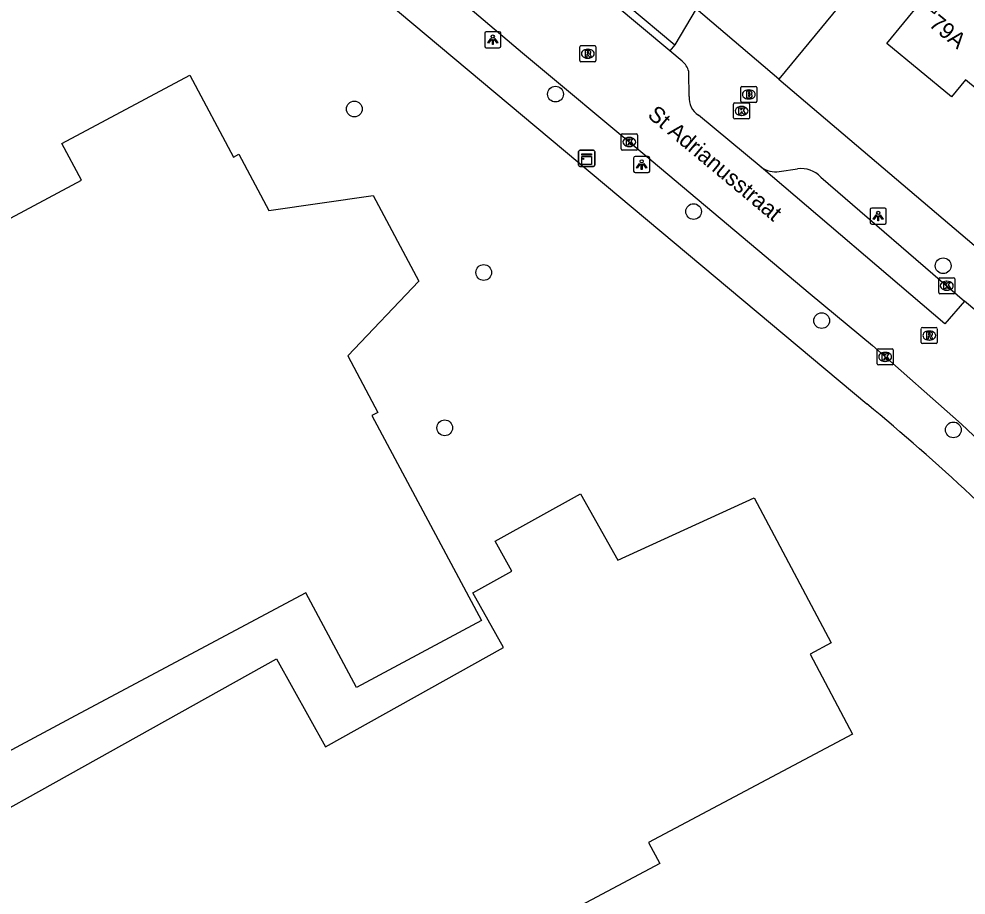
# Model space of a CAD drawing. Extents: x 162074 to 163034, y 381824 to 382557.
# Drawn here: x 162521.9 to 162580.8, y 382015.9 to 382070.3 of the extents above; entities that cross this region are included whole.
import ezdxf

# ---------------------------------------------------------------- set-up
doc = ezdxf.new("R2010")
doc.units = 0
for name, color, linetype in [('IMGEO_Boom', 7, 'Continuous'), ('IMGEO_Brandkraan', 7, 'Continuous'), ('IMGEO_Kast', 7, 'Continuous'), ('IMGEO_Kolk', 7, 'Continuous'), ('IMGEO_Lichtpunt', 7, 'Continuous'), ('IMGEO_Openbare_ruimte_label', 7, 'Continuous'), ('IMGEO_Pand', 7, 'Continuous'), ('IMGEO_Pand_nummerreeks', 7, 'Continuous'), ('IMGEO_Pand_vergunning_verleend', 7, 'Continuous'), ('IMGEO_Rijbaan_lokaal_open', 7, 'Continuous'), ('IMGEO_Rioolput', 7, 'Continuous'), ('IMGEO_Voetpad_open', 7, 'Continuous')]:
    doc.layers.add(name, color=color, linetype=linetype)

msp = doc.modelspace()

# ---------------------------------------------------------------- linework, layer by layer
at = {"layer": 'IMGEO_Boom'}
for centre in [(162555.268, 382065.67), (162542.77, 382064.746), (162563.851, 382058.369), (162579.361, 382055), (162550.809, 382054.581), (162571.812, 382051.59), (162548.386, 382044.926), (162579.99, 382044.797)]:
    msp.add_circle(centre, 0.489, dxfattribs=at)
at = {"layer": 'IMGEO_Brandkraan'}
for p, q in [((162566.781, 382065.222), (162566.781, 382066.074)), ((162566.856, 382066.148), (162567.708, 382066.148)), ((162567.782, 382066.074), (162567.782, 382065.222)), ((162567.292, 382065.368), (162567.267, 382065.368)), ((162567.269, 382065.928), (162567.294, 382065.928)), ((162567.708, 382065.148), (162566.856, 382065.148))]:
    msp.add_line(p, q, dxfattribs=at)
for points in [[(162566.781, 382065.222), (162566.781, 382066.074)], [(162566.856, 382066.148), (162567.708, 382066.148)], [(162567.782, 382066.074), (162567.782, 382065.222)], [(162567.129, 382065.848), (162567.129, 382065.448), (162567.342, 382065.448)], [(162567.36, 382065.848), (162567.129, 382065.848)], [(162567.308, 382065.767), (162567.254, 382065.767), (162567.254, 382065.691)], [(162567.254, 382065.691), (162567.307, 382065.691)], [(162567.316, 382065.615), (162567.254, 382065.615), (162567.254, 382065.534)], [(162567.254, 382065.534), (162567.316, 382065.534)], [(162567.708, 382065.148), (162566.856, 382065.148)]]:
    msp.add_lwpolyline(points, dxfattribs=at)
for centre, radius, start, end in [((162566.858, 382066.072), 0.0765, 91.55205, 178.44795), ((162566.858, 382066.072), 0.0765, 91.55205, 178.44795), ((162567.706, 382066.072), 0.0765, 1.55205, 88.44795), ((162567.706, 382066.072), 0.0765, 1.55205, 88.44795), ((162567.309, 382065.729), 0.0379, 267.82845, 90.93552), ((162567.317, 382065.574), 0.0404, 269.87594, 90.50774), ((162567.348, 382065.699), 0.251, 268.66757, 293.53466), ((162567.364, 382065.703), 0.145, 59.4692, 91.53667), ((162567.389, 382065.75), 0.0922, 285.51372, 58.15012), ((162567.394, 382065.558), 0.105, 301.31148, 78.98903), ((162566.858, 382065.224), 0.0765, 181.55205, 268.44795), ((162566.858, 382065.224), 0.0765, 181.55205, 268.44795), ((162567.706, 382065.224), 0.0765, 271.55205, 358.44795), ((162567.706, 382065.224), 0.0765, 271.55205, 358.44795)]:
    msp.add_arc(centre, radius, start, end, dxfattribs=at)
for centre, major_axis, ratio, start_param, end_param in [((162567.268, 382065.648), (-0.387, 0.002), 0.722429, 4.712389, 7.853982), ((162567.293, 382065.648), (-0.39, 0.002), 0.717154, 1.570796, 4.712389)]:
    msp.add_ellipse(centre, major_axis=major_axis, ratio=ratio, start_param=start_param, end_param=end_param, dxfattribs=at)
at = {"layer": 'IMGEO_Kast'}
for p, q in [((162556.707, 382061.252), (162556.707, 382062.093)), ((162556.707, 382062.093), (162556.707, 382061.252)), ((162556.782, 382062.177), (162557.623, 382062.177)), ((162557.623, 382062.177), (162556.782, 382062.177)), ((162557.707, 382062.102), (162557.707, 382061.261)), ((162557.707, 382061.261), (162557.707, 382062.102)), ((162557.632, 382061.177), (162556.791, 382061.177)), ((162556.791, 382061.177), (162557.632, 382061.177))]:
    msp.add_line(p, q, dxfattribs=at)
for points in [[(162556.902, 382061.967), (162557.502, 382061.967), (162557.502, 382061.882), (162556.902, 382061.882), (162556.902, 382061.967)], [(162556.902, 382061.792), (162557.502, 382061.792), (162557.502, 382061.303), (162556.902, 382061.303), (162556.902, 382061.792)]]:
    msp.add_lwpolyline(points, dxfattribs=at)
msp.add_circle((162556.986, 382061.641), 0.0377, dxfattribs=at)
for centre, start, end in [((162556.785, 382062.099), 92.4484, 184.28452), ((162556.785, 382062.099), 92.4484, 184.28452), ((162557.629, 382062.099), 2.4484, 94.28452), ((162557.629, 382062.099), 2.4484, 94.28452), ((162556.785, 382061.255), 182.4484, 274.28452), ((162556.785, 382061.255), 182.4484, 274.28452), ((162557.629, 382061.255), 272.4484, 4.28452), ((162557.629, 382061.255), 272.4484, 4.28452)]:
    msp.add_arc(centre, 0.0779, start, end, dxfattribs=at)
at = {"layer": 'IMGEO_Kolk'}
for p, q in [((162566.334, 382064.198), (162566.334, 382065.05)), ((162566.409, 382065.124), (162567.261, 382065.124)), ((162566.822, 382064.904), (162566.847, 382064.904)), ((162567.335, 382065.05), (162567.335, 382064.198)), ((162566.845, 382064.344), (162566.82, 382064.344)), ((162567.261, 382064.124), (162566.409, 382064.124)), ((162559.355, 382062.267), (162559.355, 382063.119)), ((162559.43, 382063.193), (162560.282, 382063.193)), ((162560.356, 382063.119), (162560.356, 382062.267)), ((162559.866, 382062.413), (162559.841, 382062.413)), ((162559.843, 382062.973), (162559.868, 382062.973)), ((162560.282, 382062.193), (162559.43, 382062.193)), ((162579.083, 382053.332), (162579.083, 382054.184)), ((162579.158, 382054.258), (162580.01, 382054.258)), ((162580.084, 382054.184), (162580.084, 382053.332)), ((162579.571, 382054.038), (162579.596, 382054.038)), ((162580.01, 382053.258), (162579.158, 382053.258)), ((162579.594, 382053.478), (162579.569, 382053.478)), ((162575.257, 382048.913), (162575.257, 382049.765)), ((162575.332, 382049.839), (162576.184, 382049.839)), ((162575.745, 382049.619), (162575.77, 382049.619)), ((162576.258, 382049.765), (162576.258, 382048.913)), ((162575.768, 382049.059), (162575.743, 382049.059)), ((162576.184, 382048.839), (162575.332, 382048.839))]:
    msp.add_line(p, q, dxfattribs=at)
for points in [[(162566.334, 382064.198), (162566.334, 382065.05)], [(162566.409, 382065.124), (162567.261, 382065.124)], [(162566.655, 382064.824), (162566.778, 382064.824), (162566.778, 382064.673), (162566.908, 382064.824), (162567.072, 382064.824), (162566.926, 382064.673), (162567.079, 382064.424), (162566.927, 382064.424), (162566.842, 382064.588), (162566.778, 382064.521), (162566.778, 382064.424), (162566.655, 382064.424), (162566.655, 382064.824)], [(162567.335, 382065.05), (162567.335, 382064.198)], [(162567.261, 382064.124), (162566.409, 382064.124)], [(162559.355, 382062.267), (162559.355, 382063.119)], [(162559.43, 382063.193), (162560.282, 382063.193)], [(162560.356, 382063.119), (162560.356, 382062.267)], [(162559.676, 382062.893), (162559.799, 382062.893), (162559.799, 382062.742), (162559.929, 382062.893), (162560.093, 382062.893), (162559.947, 382062.742), (162560.1, 382062.493), (162559.948, 382062.493), (162559.863, 382062.657), (162559.799, 382062.59), (162559.799, 382062.493), (162559.676, 382062.493), (162559.676, 382062.893)], [(162560.282, 382062.193), (162559.43, 382062.193)], [(162579.083, 382053.332), (162579.083, 382054.184)], [(162579.158, 382054.258), (162580.01, 382054.258)], [(162580.084, 382054.184), (162580.084, 382053.332)], [(162579.404, 382053.958), (162579.527, 382053.958), (162579.527, 382053.807), (162579.657, 382053.958), (162579.821, 382053.958), (162579.675, 382053.807), (162579.828, 382053.558), (162579.676, 382053.558), (162579.591, 382053.722), (162579.527, 382053.655), (162579.527, 382053.558), (162579.404, 382053.558), (162579.404, 382053.958)], [(162580.01, 382053.258), (162579.158, 382053.258)], [(162575.257, 382048.913), (162575.257, 382049.765)], [(162575.332, 382049.839), (162576.184, 382049.839)], [(162575.578, 382049.539), (162575.701, 382049.539), (162575.701, 382049.388), (162575.831, 382049.539), (162575.995, 382049.539), (162575.849, 382049.388), (162576.002, 382049.139), (162575.85, 382049.139), (162575.765, 382049.303), (162575.701, 382049.236), (162575.701, 382049.139), (162575.578, 382049.139), (162575.578, 382049.539)], [(162576.258, 382049.765), (162576.258, 382048.913)], [(162576.184, 382048.839), (162575.332, 382048.839)]]:
    msp.add_lwpolyline(points, dxfattribs=at)
for centre, start, end in [((162566.411, 382065.048), 91.55205, 178.44795), ((162566.411, 382065.048), 91.55205, 178.44795), ((162567.259, 382065.048), 1.55205, 88.44795), ((162567.259, 382065.048), 1.55205, 88.44795), ((162566.411, 382064.2), 181.55205, 268.44795), ((162566.411, 382064.2), 181.55205, 268.44795), ((162567.259, 382064.2), 271.55205, 358.44795), ((162567.259, 382064.2), 271.55205, 358.44795), ((162559.432, 382063.117), 91.55205, 178.44795), ((162559.432, 382063.117), 91.55205, 178.44795), ((162560.28, 382063.117), 1.55205, 88.44795), ((162560.28, 382063.117), 1.55205, 88.44795), ((162559.432, 382062.269), 181.55205, 268.44795), ((162559.432, 382062.269), 181.55205, 268.44795), ((162560.28, 382062.269), 271.55205, 358.44795), ((162560.28, 382062.269), 271.55205, 358.44795), ((162579.16, 382054.182), 91.55205, 178.44795), ((162579.16, 382054.182), 91.55205, 178.44795), ((162580.008, 382054.182), 1.55205, 88.44795), ((162580.008, 382054.182), 1.55205, 88.44795), ((162579.16, 382053.334), 181.55205, 268.44795), ((162579.16, 382053.334), 181.55205, 268.44795), ((162580.008, 382053.334), 271.55205, 358.44795), ((162580.008, 382053.334), 271.55205, 358.44795), ((162575.334, 382049.763), 91.55205, 178.44795), ((162575.334, 382049.763), 91.55205, 178.44795), ((162576.182, 382049.763), 1.55205, 88.44795), ((162576.182, 382049.763), 1.55205, 88.44795), ((162575.334, 382048.915), 181.55205, 268.44795), ((162575.334, 382048.915), 181.55205, 268.44795), ((162576.182, 382048.915), 271.55205, 358.44795), ((162576.182, 382048.915), 271.55205, 358.44795)]:
    msp.add_arc(centre, 0.0765, start, end, dxfattribs=at)
for centre, major_axis, ratio, start_param, end_param in [((162566.821, 382064.624), (-0.387, 0.002), 0.722429, 4.712389, 7.853982), ((162566.846, 382064.624), (-0.39, 0.002), 0.717154, 1.570796, 4.712389), ((162559.842, 382062.693), (-0.387, 0.002), 0.722429, 4.712389, 7.853982), ((162559.867, 382062.693), (-0.39, 0.002), 0.717154, 1.570796, 4.712389), ((162579.57, 382053.758), (-0.387, 0.002), 0.722429, 4.712389, 7.853982), ((162579.595, 382053.758), (-0.39, 0.002), 0.717154, 1.570796, 4.712389), ((162575.744, 382049.339), (-0.387, 0.002), 0.722429, 4.712389, 7.853982), ((162575.769, 382049.339), (-0.39, 0.002), 0.717154, 1.570796, 4.712389)]:
    msp.add_ellipse(centre, major_axis=major_axis, ratio=ratio, start_param=start_param, end_param=end_param, dxfattribs=at)
at = {"layer": 'IMGEO_Lichtpunt'}
for p, q in [((162551.774, 382069.549), (162550.966, 382069.549)), ((162551.774, 382069.549), (162550.966, 382069.549)), ((162550.872, 382069.454), (162550.872, 382068.647)), ((162550.872, 382069.454), (162550.872, 382068.647)), ((162551.868, 382068.647), (162551.868, 382069.454)), ((162551.868, 382068.647), (162551.868, 382069.454)), ((162550.966, 382068.553), (162551.774, 382068.553)), ((162550.966, 382068.553), (162551.774, 382068.553)), ((162560.125, 382061.695), (162560.125, 382060.888)), ((162560.125, 382061.695), (162560.125, 382060.888)), ((162561.027, 382061.79), (162560.219, 382061.79)), ((162561.027, 382061.79), (162560.219, 382061.79)), ((162561.121, 382060.888), (162561.121, 382061.695)), ((162561.121, 382060.888), (162561.121, 382061.695)), ((162560.219, 382060.794), (162561.027, 382060.794)), ((162560.219, 382060.794), (162561.027, 382060.794)), ((162574.825, 382058.494), (162574.825, 382057.687)), ((162574.825, 382058.494), (162574.825, 382057.687)), ((162575.727, 382058.589), (162574.919, 382058.589)), ((162575.727, 382058.589), (162574.919, 382058.589)), ((162575.821, 382057.687), (162575.821, 382058.494)), ((162575.821, 382057.687), (162575.821, 382058.494)), ((162574.919, 382057.593), (162575.727, 382057.593)), ((162574.919, 382057.593), (162575.727, 382057.593))]:
    msp.add_line(p, q, dxfattribs=at)
for points in [[(162551.246, 382069.118), (162551.285, 382069.09), (162551.097, 382068.828), (162551.059, 382068.855), (162551.246, 382069.118)], [(162551.348, 382069.07), (162551.395, 382069.07), (162551.395, 382068.748), (162551.348, 382068.748), (162551.348, 382069.07)], [(162551.458, 382069.09), (162551.496, 382069.117), (162551.683, 382068.855), (162551.644, 382068.827), (162551.458, 382069.09)], [(162560.499, 382061.359), (162560.538, 382061.331), (162560.35, 382061.069), (162560.312, 382061.096), (162560.499, 382061.359)], [(162560.601, 382061.311), (162560.648, 382061.311), (162560.648, 382060.989), (162560.601, 382060.989), (162560.601, 382061.311)], [(162560.711, 382061.331), (162560.749, 382061.358), (162560.936, 382061.096), (162560.897, 382061.068), (162560.711, 382061.331)], [(162575.199, 382058.158), (162575.238, 382058.13), (162575.05, 382057.868), (162575.012, 382057.895), (162575.199, 382058.158)], [(162575.301, 382058.11), (162575.348, 382058.11), (162575.348, 382057.788), (162575.301, 382057.788), (162575.301, 382058.11)], [(162575.411, 382058.13), (162575.449, 382058.157), (162575.636, 382057.895), (162575.597, 382057.867), (162575.411, 382058.13)]]:
    msp.add_lwpolyline(points, dxfattribs=at)
for centre in [(162551.371, 382069.252), (162560.624, 382061.493), (162575.324, 382058.292)]:
    msp.add_circle(centre, 0.0994, dxfattribs=at)
for centre, start, end in [((162550.966, 382069.454), 90, 180), ((162550.966, 382069.454), 90, 180), ((162551.774, 382069.454), 0, 90), ((162551.774, 382069.454), 0, 90), ((162550.966, 382068.647), 180, 270), ((162550.966, 382068.647), 180, 270), ((162551.774, 382068.647), 270, 0), ((162551.774, 382068.647), 270, 360), ((162560.219, 382061.695), 90, 180), ((162560.219, 382061.695), 90, 180), ((162561.027, 382061.695), 0, 90), ((162561.027, 382061.695), 0, 90), ((162560.219, 382060.888), 180, 270), ((162560.219, 382060.888), 180, 270), ((162561.027, 382060.888), 270, 0), ((162561.027, 382060.888), 270, 360), ((162574.919, 382058.494), 90, 180), ((162574.919, 382058.494), 90, 180), ((162575.727, 382058.494), 0, 90), ((162575.727, 382058.494), 0, 90), ((162574.919, 382057.687), 180, 270), ((162574.919, 382057.687), 180, 270), ((162575.727, 382057.687), 270, 0), ((162575.727, 382057.687), 270, 360)]:
    msp.add_arc(centre, 0.0946, start, end, dxfattribs=at)
at = {"layer": 'IMGEO_Pand'}
for points in [[(162587.721, 382068.121), (162584.131, 382063.76), (162580.744, 382066.547), (162579.876, 382065.493), (162575.851, 382068.806), (162577.972, 382071.383), (162578.824, 382070.682), (162582.19, 382074.771)], [(162511.974, 382052.93), (162525.812, 382060.326), (162524.601, 382062.593), (162532.539, 382066.837), (162535.256, 382061.754), (162535.583, 382061.928), (162537.451, 382058.432), (162543.934, 382059.376), (162546.784, 382054.044), (162542.354, 382049.402), (162544.233, 382045.888), (162543.857, 382045.686), (162550.669, 382032.941), (162542.9, 382028.788), (162539.753, 382034.676), (162525.732, 382027.182)], [(162525.732, 382027.182), (162511.188, 382019.408)]]:
    msp.add_lwpolyline(points, dxfattribs=at)
at = {"layer": 'IMGEO_Pand_vergunning_verleend'}
msp.add_lwpolyline([(162506.081, 382012.787), (162537.921, 382030.563), (162540.97, 382025.099), (162552.035, 382031.277), (162550.142, 382034.668), (162552.563, 382036.019), (162551.527, 382037.874), (162556.827, 382040.832), (162559.133, 382036.702), (162567.615, 382040.58), (162572.407, 382031.568), (162571.087, 382030.866), (162573.731, 382025.895), (162561.053, 382019.153), (162561.748, 382017.847), (162515.96, 381993.499), (162506.081, 382012.787)], dxfattribs=at)
at = {"layer": 'IMGEO_Rijbaan_lokaal_open'}
for points in [[(162526.502, 382090.663), (162528.495, 382088.989), (162536.729, 382082.148), (162544.264, 382075.847), (162553.211, 382068.229), (162560.822, 382061.89), (162571.093, 382053.249), (162574.964, 382050.041), (162580.499, 382045.158), (162584.603, 382041.27)], [(162562.365, 382068.359), (162558.855, 382071.293), (162556.529, 382073.226)], [(162563.139, 382067.712), (162562.365, 382068.359)], [(162563.578, 382065.52), (162563.549, 382067.004), (162563.547, 382067.086)], [(162568.044, 382061.134), (162564.146, 382064.364)], [(162580.692, 382052.802), (162579.468, 382051.383), (162568.044, 382061.134)], [(162581.447, 382052.151), (162580.692, 382052.802)]]:
    msp.add_lwpolyline(points, dxfattribs=at)
for centre, radius, start, end in [((162562.385, 382066.774), 1.203, 15.00514, 51.18403), ((162564.831, 382065.418), 1.257, 175.34156, 236.99278)]:
    msp.add_arc(centre, radius, start, end, dxfattribs=at)
at = {"layer": 'IMGEO_Rioolput'}
for p, q in [((162556.777, 382067.756), (162556.777, 382068.608)), ((162556.852, 382068.682), (162557.704, 382068.682)), ((162557.265, 382068.462), (162557.29, 382068.462)), ((162557.778, 382068.608), (162557.778, 382067.756)), ((162557.288, 382067.902), (162557.263, 382067.902)), ((162557.704, 382067.682), (162556.852, 382067.682)), ((162577.995, 382050.238), (162577.995, 382051.09)), ((162578.07, 382051.164), (162578.922, 382051.164)), ((162578.483, 382050.944), (162578.508, 382050.944)), ((162578.996, 382051.09), (162578.996, 382050.238)), ((162578.922, 382050.164), (162578.07, 382050.164)), ((162578.506, 382050.384), (162578.481, 382050.384))]:
    msp.add_line(p, q, dxfattribs=at)
for points in [[(162556.777, 382067.756), (162556.777, 382068.608)], [(162556.852, 382068.682), (162557.704, 382068.682)], [(162557.366, 382068.38), (162557.114, 382068.382), (162557.114, 382067.982)], [(162557.292, 382068.301), (162557.238, 382068.301), (162557.238, 382068.22)], [(162557.778, 382068.608), (162557.778, 382067.756)], [(162557.114, 382067.982), (162557.238, 382067.982), (162557.238, 382068.144), (162557.249, 382068.144)], [(162557.238, 382068.22), (162557.29, 382068.22)], [(162557.296, 382068.115), (162557.367, 382067.982), (162557.507, 382067.982), (162557.442, 382068.108)], [(162557.704, 382067.682), (162556.852, 382067.682)], [(162577.995, 382050.238), (162577.995, 382051.09)], [(162578.07, 382051.164), (162578.922, 382051.164)], [(162578.584, 382050.862), (162578.332, 382050.864), (162578.332, 382050.464)], [(162578.51, 382050.783), (162578.456, 382050.783), (162578.456, 382050.702)], [(162578.456, 382050.702), (162578.508, 382050.702)], [(162578.996, 382051.09), (162578.996, 382050.238)], [(162578.922, 382050.164), (162578.07, 382050.164)], [(162578.332, 382050.464), (162578.456, 382050.464), (162578.456, 382050.626), (162578.467, 382050.626)], [(162578.514, 382050.597), (162578.585, 382050.464), (162578.725, 382050.464), (162578.66, 382050.59)]]:
    msp.add_lwpolyline(points, dxfattribs=at)
for centre, radius, start, end in [((162556.854, 382068.606), 0.0765, 91.55205, 178.44795), ((162556.854, 382068.606), 0.0765, 91.55205, 178.44795), ((162557.298, 382068.205), 0.0964, 77.00612, 93.18647), ((162557.312, 382068.262), 0.0378, 276.66336, 79.67722), ((162557.365, 382068.27), 0.109, 350.36119, 89.41601), ((162557.702, 382068.606), 0.0765, 1.55205, 88.44795), ((162557.702, 382068.606), 0.0765, 1.55205, 88.44795), ((162556.854, 382067.758), 0.0765, 181.55205, 268.44795), ((162556.854, 382067.758), 0.0765, 181.55205, 268.44795), ((162557.248, 382068.091), 0.0533, 26.02933, 88.69889), ((162557.274, 382068.409), 0.19, 274.7715, 282.96867), ((162557.363, 382068.27), 0.112, 277.58423, 350.98172), ((162557.347, 382068.055), 0.108, 29.51342, 73.79051), ((162557.702, 382067.758), 0.0765, 271.55205, 358.44795), ((162557.702, 382067.758), 0.0765, 271.55205, 358.44795), ((162578.072, 382051.088), 0.0765, 91.55205, 178.44795), ((162578.072, 382051.088), 0.0765, 91.55205, 178.44795), ((162578.492, 382050.891), 0.19, 274.7715, 282.96867), ((162578.516, 382050.687), 0.0964, 77.00612, 93.18647), ((162578.53, 382050.744), 0.0378, 276.66336, 79.67722), ((162578.583, 382050.752), 0.109, 350.36119, 89.41601), ((162578.581, 382050.752), 0.112, 277.58423, 350.98172), ((162578.565, 382050.537), 0.108, 29.51342, 73.79051), ((162578.92, 382051.088), 0.0765, 1.55205, 88.44795), ((162578.92, 382051.088), 0.0765, 1.55205, 88.44795), ((162578.072, 382050.24), 0.0765, 181.55205, 268.44795), ((162578.072, 382050.24), 0.0765, 181.55205, 268.44795), ((162578.466, 382050.573), 0.0533, 26.02933, 88.69889), ((162578.92, 382050.24), 0.0765, 271.55205, 358.44795), ((162578.92, 382050.24), 0.0765, 271.55205, 358.44795)]:
    msp.add_arc(centre, radius, start, end, dxfattribs=at)
for centre, major_axis, ratio, start_param, end_param in [((162557.264, 382068.182), (-0.387, 0.002), 0.722429, 4.712389, 7.853982), ((162557.289, 382068.182), (-0.39, 0.002), 0.717154, 1.570796, 4.712389), ((162578.482, 382050.664), (-0.387, 0.002), 0.722429, 4.712389, 7.853982), ((162578.507, 382050.664), (-0.39, 0.002), 0.717154, 1.570796, 4.712389)]:
    msp.add_ellipse(centre, major_axis=major_axis, ratio=ratio, start_param=start_param, end_param=end_param, dxfattribs=at)
at = {"layer": 'IMGEO_Voetpad_open'}
for points in [[(162610.06, 382116.173), (162569.158, 382066.59)], [(162521.435, 382087.22), (162523.276, 382089.432), (162574.615, 382046.411)], [(162556.848, 382073.61), (162559.766, 382071.177), (162562.684, 382068.743)], [(162564.01, 382070.969), (162562.684, 382068.743)], [(162569.158, 382066.59), (162564.01, 382070.969)], [(162562.684, 382068.743), (162562.365, 382068.359)], [(162569.158, 382066.59), (162583.359, 382054.51)], [(162569.175, 382060.862), (162570.315, 382061.024)], [(162571.751, 382060.51), (162580.692, 382052.802)]]:
    msp.add_lwpolyline(points, dxfattribs=at)
for centre, radius, start, end in [((162568.918, 382062.282), 1.443, 232.71559, 280.2393), ((162570.543, 382059.399), 1.641, 42.61531, 97.99617), ((162494.336, 381948.449), 126.654, 42.88512, 50.66569)]:
    msp.add_arc(centre, radius, start, end, dxfattribs=at)

# ---------------------------------------------------------------- texts
at = {"layer": 'IMGEO_Openbare_ruimte_label'}
msp.add_text('St Adrianusstraat', height=1, rotation=320.19443, dxfattribs=at).set_placement((162560.927, 382064.279))
at = {"layer": 'IMGEO_Pand_nummerreeks'}
msp.add_text('79A', height=1, rotation=320.67302, dxfattribs=at).set_placement((162578.416, 382069.931))

doc.saveas('drawing.dxf')
